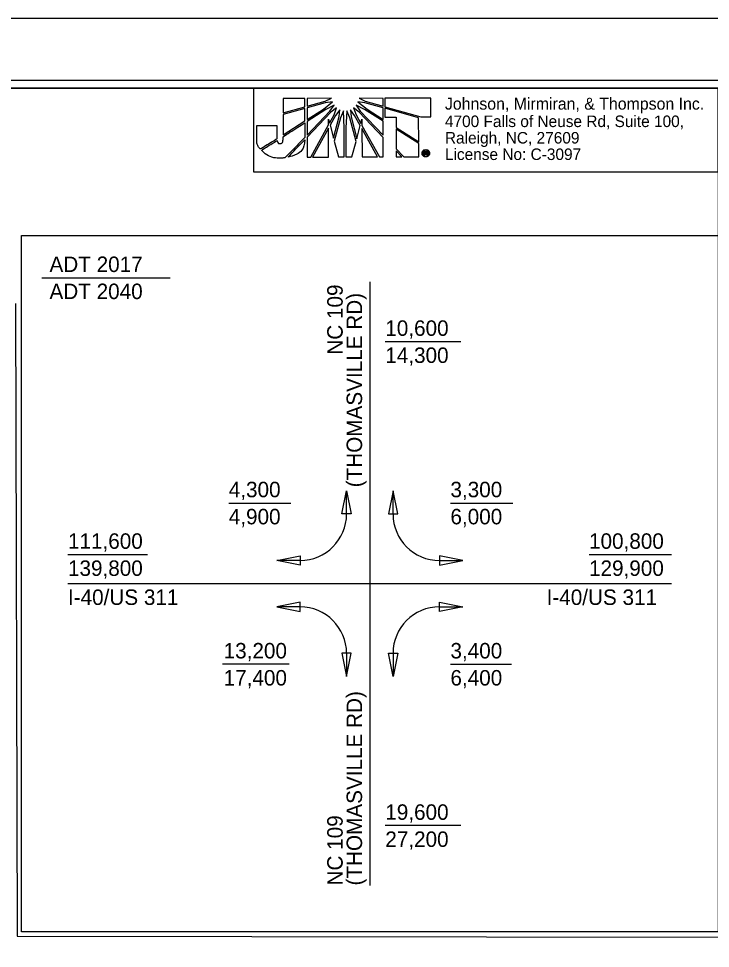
# Model space of a CAD drawing. Extents: x 1639431 to 1641888, y 841916 to 843940.
# Drawn here: x 1641444.8 to 1641668.3, y 842711 to 843011.3 of the extents above; entities that cross this region are included whole.
import ezdxf

# ---------------------------------------------------------------- set-up
doc = ezdxf.new("R2010")
doc.units = 0
for name, color, linetype in [('Default', 7, 'Continuous'), ('Prop Dimension Text', 7, 'Continuous'), ('Sheet Clip Boundary CELL', 7, 'Continuous'), ('Sheet Plan CELL', 7, 'Continuous'), ('Sheet Plot Border Inside CELL', 7, 'Continuous'), ('Sheet Plot Border Outside CELL', 7, 'Continuous')]:
    doc.layers.add(name, color=color, linetype=linetype)

msp = doc.modelspace()

# ---------------------------------------------------------------- linework, layer by layer
at = {"layer": 'Default'}
for p, q in [((1641452.28, 842927.57), (1641493.74, 842927.57)), ((1641558.25, 842926.29), (1641558.25, 842731.29)), ((1641563.25, 842906.96), (1641587.66, 842906.96)), ((1641550.75, 842851.29), (1641550.75, 842858.79)), ((1641565.75, 842851.29), (1641565.75, 842858.79)), ((1641512.69, 842854.83), (1641532.69, 842854.83)), ((1641584.29, 842854.83), (1641604.44, 842854.83)), ((1641460.75, 842838.17), (1641486.42, 842838.17)), ((1641629.06, 842838.17), (1641655.75, 842838.17)), ((1641535.75, 842836.29), (1641528.25, 842836.29)), ((1641580.75, 842836.29), (1641588.25, 842836.29)), ((1641460.75, 842828.79), (1641655.75, 842828.79)), ((1641535.75, 842821.29), (1641528.25, 842821.29)), ((1641580.75, 842821.29), (1641588.25, 842821.29)), ((1641550.75, 842806.29), (1641550.75, 842798.79)), ((1641565.75, 842806.29), (1641565.75, 842798.79)), ((1641532.22, 842802.75), (1641510.64, 842802.75)), ((1641584.29, 842802.75), (1641604.05, 842802.75)), ((1641587.66, 842750.62), (1641563.25, 842750.62))]:
    msp.add_line(p, q, dxfattribs=at)
for points in [[(1641445.75, 842716.29), (1641445.75, 842941.29), (1641670.75, 842941.29), (1641670.75, 842716.29)], [(1641550.75, 842858.79), (1641552.25, 842851.29), (1641549.25, 842851.29)], [(1641565.75, 842858.79), (1641564.25, 842851.29), (1641567.25, 842851.29)], [(1641528.25, 842836.29), (1641535.75, 842837.79), (1641535.75, 842834.79)], [(1641588.25, 842836.29), (1641580.75, 842837.79), (1641580.75, 842834.79)], [(1641528.25, 842821.29), (1641535.75, 842819.79), (1641535.75, 842822.79)], [(1641588.25, 842821.29), (1641580.75, 842819.79), (1641580.75, 842822.79)], [(1641550.75, 842798.79), (1641552.25, 842806.29), (1641549.25, 842806.29)], [(1641565.75, 842798.79), (1641564.25, 842806.29), (1641567.25, 842806.29)]]:
    msp.add_lwpolyline(points, close=True, dxfattribs=at)
for centre, start, end in [((1641535.75, 842851.29), 270, 360), ((1641580.75, 842851.29), 180, 270), ((1641535.75, 842806.29), 360, 90), ((1641580.75, 842806.29), 90, 180)]:
    msp.add_arc(centre, 15, start, end, dxfattribs=at)
at = {"layer": 'Prop Dimension Text'}
for p, q in [((1641537.24, 842985.52), (1641530.22, 842985.51)), ((1641530.22, 842985.51), (1641530.22, 842980.85)), ((1641537.24, 842982.81), (1641537.24, 842985.52)), ((1641545.87, 842985.56), (1641537.97, 842985.55)), ((1641537.97, 842985.55), (1641537.97, 842983.04)), ((1641537.97, 842983.04), (1641543.86, 842984.67)), ((1641543.86, 842984.12), (1641537.97, 842982.49)), ((1641543.24, 842982.04), (1641546.15, 842984.4)), ((1641543.86, 842984.67), (1641545.87, 842985.56)), ((1641546.15, 842984.4), (1641543.86, 842984.12)), ((1641554.42, 842984.41), (1641557.37, 842982)), ((1641556.59, 842984.13), (1641554.42, 842984.41)), ((1641562.6, 842985.54), (1641554.81, 842985.57)), ((1641554.81, 842985.57), (1641556.79, 842984.64)), ((1641562.6, 842982.48), (1641556.59, 842984.13)), ((1641556.79, 842984.64), (1641562.6, 842983.02)), ((1641562.6, 842983.02), (1641562.6, 842985.54)), ((1641577.91, 842985.59), (1641563.14, 842985.58)), ((1641563.14, 842985.58), (1641563.15, 842982.87)), ((1641577.91, 842979.54), (1641577.91, 842985.59)), ((1641530.22, 842980.85), (1641537.24, 842982.81)), ((1641537.24, 842982.3), (1641530.22, 842980.32)), ((1641537.25, 842978.23), (1641537.24, 842982.3)), ((1641537.97, 842982.49), (1641537.98, 842978.69)), ((1641537.98, 842978.69), (1641543.24, 842982.04)), ((1641544.06, 842981.95), (1641537.98, 842978.08)), ((1641537.98, 842973.7), (1641545.38, 842981.41)), ((1641545.68, 842981.03), (1641537.98, 842972.96)), ((1641546.73, 842983.31), (1641544.06, 842981.95)), ((1641545.38, 842981.41), (1641546.73, 842983.31)), ((1641547.54, 842982.47), (1641545.68, 842981.03)), ((1641546.69, 842980.22), (1641547.54, 842982.47)), ((1641548.55, 842981.84), (1641547.16, 842980.06)), ((1641548.36, 842979.68), (1641548.55, 842981.84)), ((1641549.71, 842981.53), (1641548.75, 842979.28)), ((1641550.02, 842975.99), (1641549.71, 842981.53)), ((1641550.87, 842981.53), (1641550.51, 842975.99)), ((1641551.8, 842979.29), (1641550.87, 842981.53)), ((1641551.99, 842981.85), (1641552.23, 842979.6)), ((1641553.35, 842980.06), (1641551.99, 842981.85)), ((1641552.99, 842982.47), (1641553.85, 842980.23)), ((1641554.85, 842981.04), (1641552.99, 842982.47)), ((1641553.81, 842983.32), (1641555.17, 842981.39)), ((1641556.52, 842981.97), (1641553.81, 842983.32)), ((1641562.57, 842972.91), (1641554.85, 842981.04)), ((1641555.17, 842981.39), (1641562.57, 842973.64)), ((1641562.56, 842978.14), (1641556.52, 842981.97)), ((1641557.37, 842982), (1641562.56, 842978.76)), ((1641562.56, 842978.76), (1641562.6, 842982.48)), ((1641563.15, 842982.87), (1641563.15, 842982.78)), ((1641563.15, 842982.78), (1641574.77, 842979.54)), ((1641563.15, 842982.37), (1641563.15, 842982.32)), ((1641574.03, 842979.27), (1641563.15, 842982.37)), ((1641563.15, 842982.32), (1641563.15, 842979.49)), ((1641530.22, 842980.32), (1641530.23, 842973.77)), ((1641530.23, 842973.77), (1641537.25, 842978.23)), ((1641537.98, 842978.08), (1641537.98, 842973.7)), ((1641544.87, 842976.96), (1641544.87, 842978.82)), ((1641544.87, 842978.82), (1641545.22, 842977.54)), ((1641545.22, 842977.54), (1641546.69, 842980.22)), ((1641547.16, 842980.06), (1641545.42, 842976.88)), ((1641546.54, 842972.67), (1641548.36, 842979.68)), ((1641548.75, 842979.28), (1641546.78, 842971.69)), ((1641553.82, 842971.58), (1641551.8, 842979.29)), ((1641552.23, 842979.6), (1641554.05, 842972.51)), ((1641555.17, 842976.78), (1641553.35, 842980.06)), ((1641553.85, 842980.23), (1641555.36, 842977.44)), ((1641555.36, 842977.44), (1641555.71, 842978.83)), ((1641555.71, 842978.83), (1641555.72, 842976.78)), ((1641562.57, 842973.64), (1641562.56, 842978.14)), ((1641563.15, 842979.49), (1641566.75, 842979.5)), ((1641566.75, 842979.5), (1641566.76, 842976.13)), ((1641574.04, 842971.52), (1641574.03, 842979.27)), ((1641574.77, 842979.54), (1641577.91, 842979.54)), ((1641539.15, 842966.59), (1641544.87, 842976.96)), ((1641544.87, 842975.95), (1641539.69, 842966.59)), ((1641544.93, 842966.59), (1641544.87, 842975.95)), ((1641545.42, 842976.88), (1641546.54, 842972.67)), ((1641550.02, 842966.63), (1641550.02, 842975.99)), ((1641550.51, 842975.99), (1641550.52, 842966.63)), ((1641554.05, 842972.51), (1641555.17, 842976.78)), ((1641555.72, 842976.78), (1641561.33, 842966.61)), ((1641560.75, 842966.64), (1641555.72, 842975.77)), ((1641555.72, 842975.77), (1641555.73, 842966.64)), ((1641566.76, 842976.13), (1641574.04, 842971.52)), ((1641566.76, 842975.55), (1641566.76, 842969.27)), ((1641574.04, 842970.98), (1641566.76, 842975.55)), ((1641537.98, 842972.96), (1641537.99, 842966.59)), ((1641546.78, 842971.69), (1641548.1, 842966.63)), ((1641552.47, 842966.64), (1641553.82, 842971.58)), ((1641562.57, 842966.61), (1641562.57, 842972.91)), ((1641566.76, 842969.27), (1641569.28, 842966.62)), ((1641568.59, 842966.62), (1641566.76, 842968.58)), ((1641566.76, 842968.58), (1641566.77, 842966.61)), ((1641574.04, 842966.62), (1641574.04, 842970.98)), ((1641576.33, 842968.99), (1641576.33, 842968.77)), ((1641576.33, 842968.77), (1641576.33, 842968.99)), ((1641537.99, 842966.59), (1641539.15, 842966.59)), ((1641539.69, 842966.59), (1641544.93, 842966.59)), ((1641548.1, 842966.63), (1641550.02, 842966.63)), ((1641550.52, 842966.63), (1641552.47, 842966.64)), ((1641555.73, 842966.64), (1641560.75, 842966.64)), ((1641561.33, 842966.61), (1641562.57, 842966.61)), ((1641566.77, 842966.61), (1641568.59, 842966.62)), ((1641569.28, 842966.62), (1641574.04, 842966.62)), ((1641575.89, 842967.29), (1641575.89, 842968.36)), ((1641575.89, 842968.36), (1641576.33, 842968.36)), ((1641576.13, 842967.29), (1641575.89, 842967.29)), ((1641576.33, 842968.15), (1641576.13, 842968.15)), ((1641576.13, 842968.15), (1641576.13, 842967.9)), ((1641576.13, 842967.9), (1641576.33, 842967.9)), ((1641576.33, 842967.71), (1641576.13, 842967.71)), ((1641576.13, 842967.71), (1641576.13, 842967.29)), ((1641576.33, 842968.36), (1641576.33, 842968.15)), ((1641576.33, 842968.15), (1641576.33, 842968.36)), ((1641576.33, 842968.36), (1641576.4, 842968.36)), ((1641576.36, 842968.15), (1641576.33, 842968.15)), ((1641576.33, 842967.9), (1641576.33, 842967.71)), ((1641576.33, 842967.71), (1641576.33, 842967.9)), ((1641576.33, 842967.9), (1641576.34, 842967.9)), ((1641576.34, 842967.71), (1641576.33, 842967.71)), ((1641576.33, 842966.87), (1641576.33, 842966.63)), ((1641576.33, 842966.63), (1641576.33, 842966.87)), ((1641576.33, 842966.87), (1641576.34, 842966.87)), ((1641576.34, 842966.63), (1641576.33, 842966.63))]:
    msp.add_line(p, q, dxfattribs=at)
msp.add_lwpolyline([(1641520.72, 842961.76), (1641670.75, 842961.76), (1641670.75, 842988.83), (1641520.72, 842988.83)], close=True, dxfattribs=at)
for points in [[(1641530.22, 842980.85), (1641537.24, 842982.81), (1641537.24, 842985.52), (1641530.22, 842985.51), (1641530.22, 842980.85)], [(1641543.86, 842984.67), (1641545.87, 842985.56), (1641537.97, 842985.55), (1641537.97, 842983.04), (1641543.86, 842984.67)], [(1641537.97, 842982.49), (1641537.98, 842978.69), (1641543.24, 842982.04), (1641546.15, 842984.4), (1641543.86, 842984.12), (1641537.97, 842982.49)], [(1641554.42, 842984.41), (1641557.37, 842982), (1641562.56, 842978.76), (1641562.6, 842982.48), (1641556.59, 842984.13), (1641554.42, 842984.41)], [(1641556.79, 842984.64), (1641562.6, 842983.02), (1641562.6, 842985.54), (1641554.81, 842985.57), (1641556.79, 842984.64)], [(1641577.91, 842985.59), (1641563.14, 842985.58), (1641563.15, 842982.87), (1641563.15, 842982.78), (1641574.77, 842979.54), (1641577.91, 842979.54), (1641577.91, 842985.59)], [(1641530.23, 842973.77), (1641537.25, 842978.23), (1641537.24, 842982.3), (1641530.22, 842980.32), (1641530.23, 842973.77)], [(1641537.98, 842978.08), (1641537.98, 842973.7), (1641545.38, 842981.41), (1641546.73, 842983.31), (1641544.06, 842981.95), (1641537.98, 842978.08)], [(1641547.54, 842982.47), (1641545.68, 842981.03), (1641537.98, 842972.96), (1641537.99, 842966.59), (1641539.15, 842966.59), (1641544.87, 842976.96), (1641544.87, 842978.82), (1641545.22, 842977.54), (1641546.69, 842980.22), (1641547.54, 842982.47)], [(1641548.55, 842981.84), (1641547.16, 842980.06), (1641545.42, 842976.88), (1641546.54, 842972.67), (1641548.36, 842979.68), (1641548.55, 842981.84)], [(1641548.75, 842979.28), (1641546.78, 842971.69), (1641548.1, 842966.63), (1641550.02, 842966.63), (1641550.02, 842975.99), (1641549.71, 842981.53), (1641548.75, 842979.28)], [(1641550.87, 842981.53), (1641550.51, 842975.99), (1641550.52, 842966.63), (1641552.47, 842966.64), (1641553.82, 842971.58), (1641551.8, 842979.29), (1641550.87, 842981.53)], [(1641551.99, 842981.85), (1641552.23, 842979.6), (1641554.05, 842972.51), (1641555.17, 842976.78), (1641553.35, 842980.06), (1641551.99, 842981.85)], [(1641552.99, 842982.47), (1641553.85, 842980.23), (1641555.36, 842977.44), (1641555.71, 842978.83), (1641555.72, 842976.78), (1641561.33, 842966.61), (1641562.57, 842966.61), (1641562.57, 842972.91), (1641554.85, 842981.04), (1641552.99, 842982.47)], [(1641553.81, 842983.32), (1641555.17, 842981.39), (1641562.57, 842973.64), (1641562.56, 842978.14), (1641556.52, 842981.97), (1641553.81, 842983.32)], [(1641563.15, 842982.37), (1641563.15, 842982.32), (1641563.15, 842979.49), (1641566.75, 842979.5), (1641566.76, 842976.13), (1641574.04, 842971.52), (1641574.03, 842979.27), (1641563.15, 842982.37)], [(1641539.69, 842966.59), (1641544.93, 842966.59), (1641544.87, 842975.95), (1641539.69, 842966.59)], [(1641555.73, 842966.64), (1641560.75, 842966.64), (1641555.72, 842975.77), (1641555.73, 842966.64)], [(1641566.76, 842975.55), (1641566.76, 842969.27), (1641569.28, 842966.62), (1641574.04, 842966.62), (1641574.04, 842970.98), (1641566.76, 842975.55), (1641566.76, 842975.55)], [(1641566.77, 842966.61), (1641566.77, 842966.61), (1641568.59, 842966.62), (1641566.76, 842968.58), (1641566.77, 842966.61)], [(1641576.8, 842967.54), (1641576.8, 842967.48), (1641576.81, 842967.44), (1641576.81, 842967.4), (1641576.84, 842967.29), (1641576.61, 842967.29)]]:
    msp.add_lwpolyline(points, dxfattribs=at)
for points, degree in [([(1641529.22, 842970.93), (1641528.81, 842970.93), (1641528.45, 842971.17), (1641528.3, 842971.94), (1641528.3, 842971.94), (1641523.26, 842968.82), (1641523.26, 842968.82), (1641524.81, 842967.19), (1641527.29, 842966.22), (1641529.39, 842966.22), (1641529.94, 842966.22), (1641530.35, 842966.27), (1641530.93, 842966.38), (1641530.93, 842966.38), (1641537.25, 842972.92), (1641537.25, 842972.92), (1641537.25, 842972.92), (1641537.25, 842977.65), (1641537.25, 842977.65), (1641537.25, 842977.65), (1641530.23, 842973.18), (1641530.23, 842973.18), (1641530.23, 842971.41), (1641529.8, 842970.93), (1641529.22, 842970.93)], 3), ([(1641529.22, 842970.93), (1641528.81, 842970.93), (1641528.45, 842971.17), (1641528.3, 842971.94), (1641528.3, 842971.94), (1641523.26, 842968.82), (1641523.26, 842968.82), (1641524.81, 842967.19), (1641527.29, 842966.22), (1641529.39, 842966.22), (1641529.94, 842966.22), (1641530.35, 842966.27), (1641530.93, 842966.38), (1641530.93, 842966.38), (1641537.25, 842972.92), (1641537.25, 842972.92), (1641537.25, 842972.92), (1641537.25, 842977.65), (1641537.25, 842977.65), (1641537.25, 842977.65), (1641530.23, 842973.18), (1641530.23, 842973.18), (1641530.23, 842971.41), (1641529.8, 842970.93), (1641529.22, 842970.93)], 3), ([(1641528.21, 842976.78), (1641528.21, 842976.78), (1641521.71, 842976.78), (1641521.71, 842976.78), (1641521.71, 842976.78), (1641521.72, 842972.71), (1641521.72, 842972.71), (1641521.72, 842972.71), (1641521.72, 842972.28), (1641521.72, 842972.28), (1641521.72, 842971.01), (1641522.13, 842970), (1641522.88, 842969.16), (1641522.88, 842969.16), (1641528.22, 842972.4), (1641528.22, 842972.49), (1641528.22, 842972.49), (1641528.21, 842976.78), (1641528.21, 842976.78)], 3), ([(1641537.25, 842972.18), (1641537.25, 842972.18), (1641531.79, 842966.53), (1641531.79, 842966.53), (1641534.46, 842967.2), (1641537.13, 842968.97), (1641537.25, 842972.18)], 3), ([(1641576.33, 842966.63), (1641576.01, 842966.63), (1641575.72, 842966.75), (1641575.49, 842966.98), (1641575.26, 842967.21), (1641575.14, 842967.49), (1641575.14, 842967.82), (1641575.14, 842968.15), (1641575.25, 842968.44), (1641575.49, 842968.65), (1641575.72, 842968.88), (1641576, 842968.99), (1641576.33, 842968.99)], 3), ([(1641576.33, 842968.77), (1641576.06, 842968.77), (1641575.84, 842968.68), (1641575.65, 842968.5), (1641575.47, 842968.32), (1641575.37, 842968.09), (1641575.37, 842967.82), (1641575.37, 842967.56), (1641575.47, 842967.32), (1641575.66, 842967.14), (1641575.84, 842966.95), (1641576.07, 842966.87), (1641576.33, 842966.87)], 3), ([(1641576.33, 842968.99), (1641576.66, 842968.99), (1641576.94, 842968.88), (1641577.18, 842968.65), (1641577.41, 842968.44), (1641577.53, 842968.16), (1641577.53, 842967.82)], 3), ([(1641576.34, 842966.87), (1641576.6, 842966.87), (1641576.83, 842966.95), (1641577.01, 842967.14), (1641577.2, 842967.33), (1641577.29, 842967.56), (1641577.29, 842967.82), (1641577.29, 842968.09), (1641577.2, 842968.32), (1641577.01, 842968.51), (1641576.83, 842968.68), (1641576.6, 842968.77), (1641576.33, 842968.77)], 3), ([(1641576.34, 842967.9), (1641576.49, 842967.9), (1641576.57, 842967.95), (1641576.57, 842968.04), (1641576.57, 842968.12), (1641576.5, 842968.15), (1641576.36, 842968.15)], 3), ([(1641577.53, 842967.82), (1641577.53, 842967.49), (1641577.41, 842967.21), (1641577.19, 842966.97), (1641576.95, 842966.75), (1641576.67, 842966.63), (1641576.34, 842966.63)], 3), ([(1641576.52, 842967.67), (1641576.49, 842967.69), (1641576.44, 842967.71), (1641576.34, 842967.71)], 2), ([(1641576.4, 842968.36), (1641576.67, 842968.36), (1641576.81, 842968.25), (1641576.81, 842968.04), (1641576.81, 842967.94), (1641576.77, 842967.86), (1641576.68, 842967.8)], 3), ([(1641576.61, 842967.29), (1641576.58, 842967.34), (1641576.56, 842967.4), (1641576.56, 842967.48), (1641576.56, 842967.58), (1641576.55, 842967.64), (1641576.52, 842967.67)], 3), ([(1641576.68, 842967.8), (1641576.75, 842967.76), (1641576.79, 842967.68), (1641576.8, 842967.54)], 2)]:
    msp.add_open_spline(points, degree=degree, dxfattribs=at)
at = {"layer": 'Sheet Clip Boundary CELL'}
msp.add_lwpolyline([(1641443.85, 842919.31), (1641444.34, 842714.97), (1641747.5, 842714.54), (1641796.56, 842667.29), (1641752.38, 842181.83), (1641755.49, 842119.21), (1641627.07, 841958.82)], dxfattribs=at)
at = {"layer": 'Sheet Plan CELL'}
for points in [[(1640370.79, 841938.82), (1640370.76, 842988.79), (1641670.75, 842988.83), (1641670.76, 842838.77), (1641870.8, 842838.76), (1641870.8, 841938.82)], [(1641870.83, 842988.82), (1640370.79, 842988.82), (1640370.79, 841938.82), (1641870.8, 841938.82)]]:
    msp.add_lwpolyline(points, close=True, dxfattribs=at)
at = {"layer": 'Sheet Plot Border Inside CELL'}
msp.add_lwpolyline([(1640217.3, 841936.31), (1641883.29, 841936.32), (1641883.3, 842991.31), (1640217.3, 842991.31)], close=True, dxfattribs=at)
at = {"layer": 'Sheet Plot Border Outside CELL'}
msp.add_lwpolyline([(1640204.3, 841916.31), (1641887.8, 841916.31), (1641887.8, 843011.31), (1640204.3, 843011.31)], close=True, dxfattribs=at)
msp.add_lwpolyline([(1640204.3, 841916.31), (1641887.8, 841916.31), (1641887.8, 843011.31), (1640204.3, 843011.31)], close=True, dxfattribs=at)

# ---------------------------------------------------------------- texts
at = {"layer": 'Default'}
for s, rotation, p in [('ADT 2017', 360, (1641454.78, 842929.45)), ('ADT 2040', 360, (1641454.78, 842920.7)), ('NC 109', 90, (1641549.49, 842902.75)), ('(THOMASVILLE RD)', 90, (1641555.75, 842859.91)), ('10,600', 360, (1641563.25, 842908.83)), ('14,300', 360, (1641563.25, 842900.08)), ('4,300', 360, (1641512.69, 842856.7)), ('3,300', 360, (1641584.29, 842856.7)), ('4,900', 360, (1641512.69, 842847.95)), ('6,000', 360, (1641584.29, 842847.95)), ('111,600', 360, (1641460.75, 842840.04)), ('100,800', 360, (1641629.06, 842840.04)), ('139,800', 360, (1641460.75, 842831.29)), ('129,900', 360, (1641629.06, 842831.29)), ('I-40/US 311', 360, (1641460.75, 842821.91)), ('I-40/US 311', 360, (1641615.36, 842821.91)), ('13,200', 360, (1641511.03, 842804.63)), ('3,400', 360, (1641584.29, 842804.63)), ('17,400', 360, (1641511.03, 842795.88)), ('6,400', 360, (1641584.29, 842795.88)), ('(THOMASVILLE RD)', 90, (1641555.75, 842731.29)), ('19,600', 360, (1641563.25, 842752.5)), ('NC 109', 90, (1641549.49, 842731.29)), ('27,200', 360, (1641563.25, 842743.75))]:
    msp.add_text(s, height=5, rotation=rotation, dxfattribs=at).set_placement(p)
at = {"layer": 'Prop Dimension Text'}
for s, height, p in [('Johnson, Mirmiran, & Thompson Inc.', 3.8334, (1641582.51, 842981.9)), ('4700 Falls of Neuse Rd, Suite 100, ', 3.7239, (1641582.51, 842976.27)), ('Raleigh, NC, 27609', 3.7239, (1641582.51, 842970.95)), ('License No: C-3097', 3.7239, (1641582.51, 842965.63))]:
    msp.add_text(s, height=height, dxfattribs=at).set_placement(p)

doc.saveas('drawing.dxf')
